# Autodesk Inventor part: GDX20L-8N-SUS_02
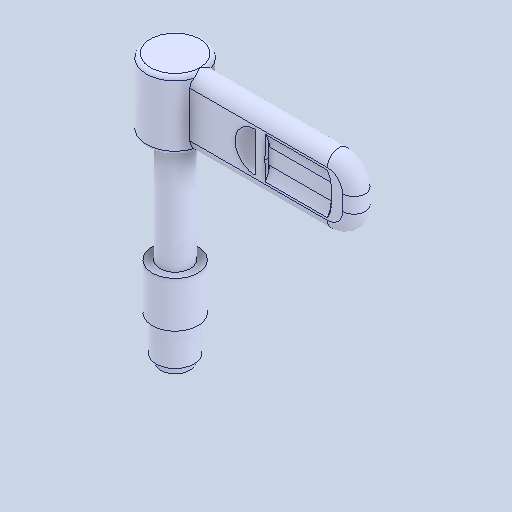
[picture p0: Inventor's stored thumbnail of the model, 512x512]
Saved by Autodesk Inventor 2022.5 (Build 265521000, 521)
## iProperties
Created: 2024-06
Part Number: GDX20L-8N-SUS_02
Material: 一般
Document SubType Name: Modeling
Designer: ImaoCorp
Density: 1 g/cm^3
Appearance: 既定
Author: ImaoCorp
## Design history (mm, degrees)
feature "GDX20L-8N-SUS_02"
node "ソリッド1"
